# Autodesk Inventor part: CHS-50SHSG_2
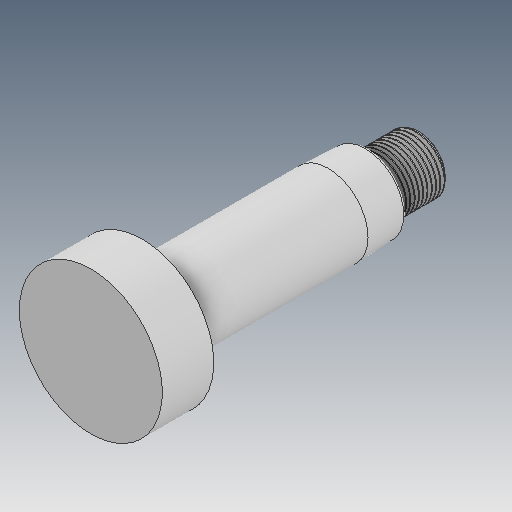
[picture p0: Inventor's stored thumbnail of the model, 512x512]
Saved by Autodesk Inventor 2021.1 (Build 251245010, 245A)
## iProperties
Created: 2019-04
Part Number: CHS-50SHSG_2
Material: Ogólny
Document SubType Name: Modeling
Designer: user
Density: 1 g/cm^3
Appearance: Domyślna
Author: user
Revision Number: ÈÎºÎ
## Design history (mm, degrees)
feature "ÊäÈë1"
node "Bryła1"
